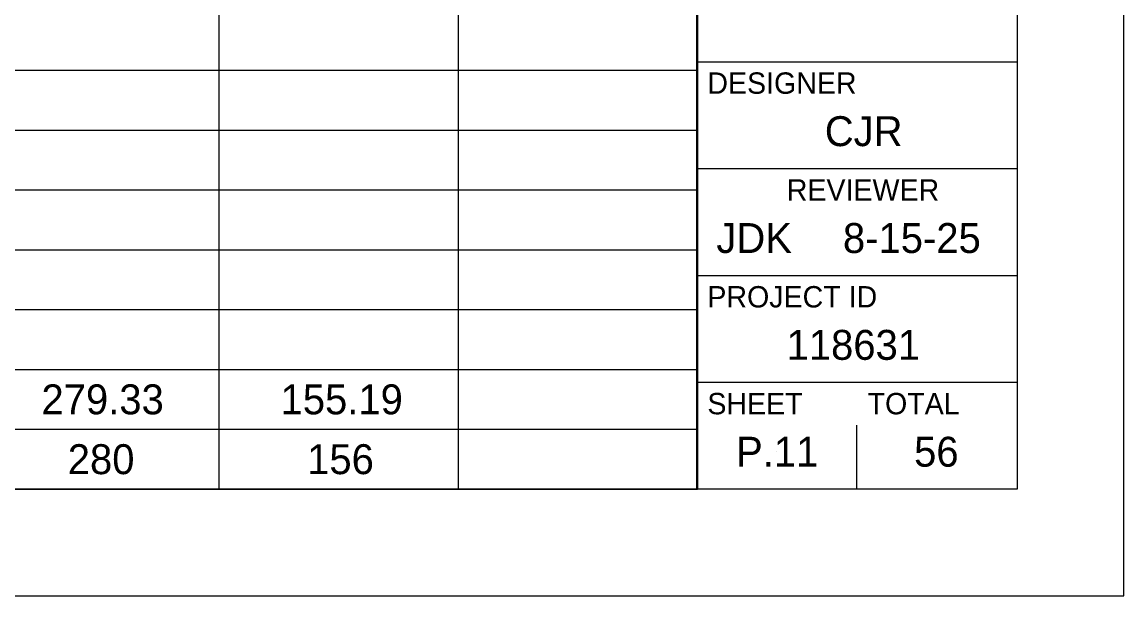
# Model space of a CAD drawing. Extents: x 0 to 34, y 0 to 22.
# Drawn here: x 28.84 to 34, y 0 to 2.69 of the extents above; entities that cross this region are included whole.
import ezdxf

# ---------------------------------------------------------------- set-up
doc = ezdxf.new("R2010")
doc.units = 0
for name, color, linetype in [('Default', 7, 'Continuous'), ('SH_Border', 7, 'Continuous'), ('SH_Cut_Line', 7, 'Continuous'), ('SH_Data', 7, 'Continuous')]:
    doc.layers.add(name, color=color, linetype=linetype)

msp = doc.modelspace()

# ---------------------------------------------------------------- linework, layer by layer
at = {"layer": 'SH_Border'}
for p, q in [((32, 0.5), (32, 21.5)), ((32, 2.5), (33.5, 2.5)), ((32, 2), (33.5, 2)), ((32, 1.5), (33.5, 1.5)), ((32, 1), (33.5, 1))]:
    msp.add_line(p, q, dxfattribs=at)
msp.add_lwpolyline([(1.5, 21.5), (33.5, 21.5), (33.5, 0.5), (1.5, 0.5)], close=True, dxfattribs=at)
at = {"layer": 'SH_Cut_Line'}
msp.add_lwpolyline([(0, 0), (34, 0), (34, 22), (0, 22)], close=True, dxfattribs=at)
at = {"layer": 'SH_Data'}
for p, q in [((29.7635, 21.5), (29.7635, 0.5)), ((30.8836, 21.5), (30.8836, 0.5)), ((32.0036, 21.5), (32.0036, 0.5)), ((1.5, 2.46), (32.0036, 2.46)), ((1.5, 2.18), (32.0036, 2.18)), ((1.5, 1.9), (32.0036, 1.9)), ((1.5, 1.62), (32.0036, 1.62)), ((1.5, 1.34), (32.0036, 1.34)), ((1.5, 1.06), (32.0036, 1.06)), ((1.5, 0.78), (32.0036, 0.78)), ((32.75, 0.5), (32.75, 0.8)), ((32.375, 0.675), (32.375, 0.675)), ((1.5, 0.5), (32.0036, 0.5))]:
    msp.add_line(p, q, dxfattribs=at)

# ---------------------------------------------------------------- texts
at = {"layer": 'Default'}
for s, p in [('279.33', (28.9331, 0.85)), ('155.19', (30.0521, 0.85)), ('280', (29.0561, 0.57)), ('156', (30.1766, 0.57))]:
    msp.add_text(s, height=0.14, dxfattribs=at).set_placement(p)
at = {"layer": 'SH_Data'}
for s, height, p in [('DESIGNER', 0.1, (32.05, 2.35)), ('CJR', 0.14, (32.5996, 2.105)), ('REVIEWER', 0.1, (32.4218, 1.85)), ('JDK', 0.14, (32.0923, 1.605)), ('8-15-25', 0.14, (32.6845, 1.605)), ('PROJECT ID', 0.1, (32.05, 1.35)), ('118631', 0.14, (32.4208, 1.105)), ('SHEET', 0.1, (32.05, 0.85)), ('TOTAL', 0.1, (32.8, 0.85)), ('P.11', 0.14, (32.1844, 0.605)), ('56', 0.14, (33.0176, 0.605))]:
    msp.add_text(s, height=height, dxfattribs=at).set_placement(p)

doc.saveas('drawing.dxf')
